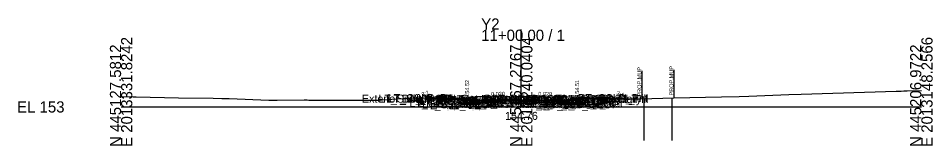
# Model space of a CAD drawing. Extents: x -26 to 203, y -10 to 6017.
# Drawn here: x -25.7 to 202.8, y 1990.3 to 2022.2 of the extents above; entities that cross this region are included whole.
import ezdxf

# ---------------------------------------------------------------- set-up
doc = ezdxf.new("R2010")
doc.units = 0
for name, color, linetype in [('Default', 7, 'Continuous'), ('Exist CMT Pavement', 7, 'Continuous'), ('Exist Cross Section Cell', 7, 'Continuous'), ('Exist XS Center Line Elevation Label', 7, 'Continuous'), ('Exist XS Ground Line', 7, 'Continuous'), ('Prop CMT Conc Surface', 7, 'Continuous'), ('Prop CMT Concrete Structures', 7, 'Continuous'), ('Prop CMT Pvmt Course 1', 7, 'Continuous'), ('Prop CMT Pvmt Course 1 CG', 7, 'Continuous'), ('Prop CMT Pvmt Course 1 Wedge', 7, 'Continuous'), ('Prop CMT Pvmt Course 2', 7, 'Continuous'), ('Prop CMT Pvmt Course 3', 7, 'Continuous'), ('Prop CMT Pvmt Surface', 7, 'Continuous'), ('Prop CMT Pvmt Wedge Surface 1', 7, 'Continuous'), ('Prop CMT Pvmt Wedge Surface 2', 7, 'Continuous'), ('Prop CMT Pvmt Wedge Surface 3', 7, 'Continuous'), ('Prop CMT Slope Grass', 7, 'Continuous'), ('Prop CMT Subgrade Earthwork', 7, 'Continuous'), ('Prop XS Earthwork Shape', 7, 'Continuous'), ('Prop XS Hydro Elevations', 7, 'Continuous'), ('Prop XS Label Text', 7, 'Continuous'), ('Prop XS SE Text', 7, 'Continuous'), ('Prop XS Side Slope Text', 7, 'Continuous'), ('Scratch_Level_0', 7, 'Continuous'), ('Scratch_Level_1', 7, 'Continuous')]:
    doc.layers.add(name, color=color, linetype=linetype)

msp = doc.modelspace()

# ---------------------------------------------------------------- linework, layer by layer
at = {"layer": 'Exist CMT Pavement'}
msp.add_lwpolyline([(89.49, 2001.72), (90.19, 2001.57), (91.02, 2001.56), (100, 2001.76), (100.76, 2001.78), (102.04, 2001.79), (110.95, 2001.68), (110.96, 2001.68)], dxfattribs=at)
at = {"layer": 'Exist Cross Section Cell'}
for p, q in [((100, 2000), (100, 2019.31)), ((0, 2000), (100, 2000)), ((100, 2000), (200, 2000))]:
    msp.add_line(p, q, dxfattribs=at)
at = {"layer": 'Exist XS Ground Line'}
msp.add_lwpolyline([(0, 2002.63), (2.99, 2002.56), (3.44, 2002.55), (3.78, 2002.54), (14.33, 2002.29), (22.98, 2002.18), (25.2, 2002.13), (26.49, 2002.12), (27.02, 2002.11), (36.96, 2001.73), (37.88, 2001.73), (39.03, 2001.72), (45.77, 2001.74), (46.15, 2001.74), (46.54, 2001.74), (46.94, 2001.73), (47.25, 2001.73), (53.38, 2001.7), (56.55, 2001.69), (57.92, 2001.68), (64.16, 2001.69), (68.82, 2002), (71.76, 2002.13), (87.86, 2001.87), (88.85, 2001.87), (90.19, 2001.57), (91.02, 2001.56), (100, 2001.76), (100.76, 2001.78), (102.04, 2001.79), (110.95, 2001.68), (112.62, 2001.98), (112.94, 2002.02), (114.7, 2002), (117.25, 2002.02), (122.01, 2002.03), (127.25, 2002.02), (129.89, 2002.02), (138.15, 2002.29), (150.06, 2002.49), (154.43, 2002.64), (156.88, 2002.69), (166.9, 2003.11), (169.95, 2003.21), (193.73, 2003.93), (194.93, 2003.97), (195.59, 2003.98), (196.48, 2004.04), (200, 2004.1)], dxfattribs=at)
at = {"layer": 'Prop CMT Conc Surface'}
for points in [[(86.49, 2001.52), (86.49, 2002.02), (85.99, 2002.02)], [(113.97, 2001.51), (113.97, 2002.01), (114.47, 2002.01)], [(88.49, 2001.64), (86.49, 2001.52)], [(111.97, 2001.63), (113.97, 2001.51)]]:
    msp.add_lwpolyline(points, dxfattribs=at)
at = {"layer": 'Prop CMT Concrete Structures'}
for points in [[(88.49, 2001.64), (86.49, 2001.52), (86.49, 2002.02), (85.99, 2002.02)], [(85.99, 2002.02), (85.99, 2001), (88.49, 2001.05)], [(111.97, 2001.63), (113.97, 2001.51), (113.97, 2002.01), (114.47, 2002.01)], [(114.47, 2002.01), (114.47, 2001), (111.97, 2001.05)], [(88.49, 2001.05), (88.49, 2001.64)], [(111.97, 2001.05), (111.97, 2001.63)]]:
    msp.add_lwpolyline(points, dxfattribs=at)
at = {"layer": 'Prop CMT Pvmt Course 1'}
for points in [[(100, 2001.87), (88.49, 2001.64)], [(88.49, 2001.64), (88.49, 2001.39)], [(88.49, 2001.39), (89.49, 2001.41)], [(89.49, 2001.53), (100, 2001.74)], [(89.49, 2001.41), (89.49, 2001.53)], [(100, 2001.62), (100, 2001.87)], [(100, 2001.87), (111.97, 2001.63)], [(100, 2001.62), (100, 2001.87)], [(100, 2001.74), (100, 2001.62), (100, 2001.62)], [(110.97, 2001.52), (100, 2001.74)], [(100, 2001.74), (100, 2001.62), (100, 2001.62)], [(110.97, 2001.4), (110.97, 2001.52)], [(111.97, 2001.38), (110.97, 2001.4)], [(111.97, 2001.63), (111.97, 2001.38)]]:
    msp.add_lwpolyline(points, dxfattribs=at)
at = {"layer": 'Prop CMT Pvmt Course 1 CG'}
for points in [[(88.49, 2001.05), (85.49, 2000.99), (85.15, 2000.65)], [(85.15, 2000.65), (88.49, 2000.72)], [(88.49, 2000.72), (88.49, 2001.05)], [(111.97, 2001.05), (114.97, 2000.99), (115.31, 2000.65)], [(111.97, 2000.71), (111.97, 2001.05)], [(115.31, 2000.65), (111.97, 2000.71)]]:
    msp.add_lwpolyline(points, dxfattribs=at)
at = {"layer": 'Prop CMT Pvmt Course 1 Wedge'}
for points in [[(92.23, 2001.59), (91.02, 2001.56), (90.93, 2001.56)], [(90.93, 2001.56), (91.02, 2001.56)], [(91.02, 2001.56), (92.23, 2001.59)]]:
    msp.add_lwpolyline(points, dxfattribs=at)
at = {"layer": 'Prop CMT Pvmt Course 2'}
for points in [[(89.49, 2001.41), (88.49, 2001.39)], [(88.49, 2001.39), (88.49, 2001.05)], [(88.49, 2001.05), (89.49, 2001.07)], [(89.49, 2001.07), (89.49, 2001.41)], [(110.97, 2001.07), (110.97, 2001.4)], [(110.97, 2001.4), (111.97, 2001.38)], [(111.97, 2001.05), (110.97, 2001.07)], [(111.97, 2001.38), (111.97, 2001.05)]]:
    msp.add_lwpolyline(points, dxfattribs=at)
at = {"layer": 'Prop CMT Pvmt Course 3'}
for points in [[(89.49, 2001.07), (88.49, 2001.05)], [(88.49, 2001.05), (88.49, 2000.72)], [(88.49, 2000.72), (89.49, 2000.74)], [(89.49, 2000.74), (89.49, 2001.07)], [(110.97, 2001.07), (111.97, 2001.05)], [(110.97, 2000.73), (110.97, 2001.07)], [(111.97, 2000.71), (110.97, 2000.73)], [(111.97, 2001.05), (111.97, 2000.71)]]:
    msp.add_lwpolyline(points, dxfattribs=at)
at = {"layer": 'Prop CMT Pvmt Surface'}
for points in [[(100, 2001.87), (88.49, 2001.64)], [(100, 2001.87), (111.97, 2001.63)]]:
    msp.add_lwpolyline(points, dxfattribs=at)
at = {"layer": 'Prop CMT Pvmt Wedge Surface 1'}
for points in [[(88.49, 2001.39), (88.49, 2001.64)], [(89.49, 2001.41), (88.49, 2001.39)], [(100, 2001.74), (89.49, 2001.53)], [(89.49, 2001.53), (89.49, 2001.41)], [(100, 2001.74), (110.97, 2001.52)], [(110.97, 2001.52), (110.97, 2001.4)], [(110.97, 2001.4), (111.97, 2001.38)], [(111.97, 2001.38), (111.97, 2001.63)]]:
    msp.add_lwpolyline(points, dxfattribs=at)
at = {"layer": 'Prop CMT Pvmt Wedge Surface 2'}
for points in [[(88.49, 2001.39), (88.49, 2001.64)], [(100, 2001.62), (88.49, 2001.39)], [(100, 2001.62), (111.97, 2001.38)], [(111.97, 2001.38), (111.97, 2001.63)]]:
    msp.add_lwpolyline(points, dxfattribs=at)
at = {"layer": 'Prop CMT Pvmt Wedge Surface 3'}
for points in [[(88.49, 2001.05), (88.49, 2001.64)], [(100, 2001.28), (88.49, 2001.05)], [(100, 2001.28), (111.97, 2001.05)], [(111.97, 2001.05), (111.97, 2001.63)]]:
    msp.add_lwpolyline(points, dxfattribs=at)
at = {"layer": 'Prop CMT Slope Grass'}
for points in [[(85.99, 2002.02), (76.49, 2002.21), (76.05, 2002.06)], [(114.47, 2002.01), (123.97, 2002.2), (124.5, 2002.02)]]:
    msp.add_lwpolyline(points, dxfattribs=at)
at = {"layer": 'Prop CMT Subgrade Earthwork'}
for points in [[(88.49, 2000.72), (85.15, 2000.65), (83.74, 2002.06)], [(111.97, 2000.71), (115.31, 2000.65), (116.72, 2002.05)], [(89.49, 2000.74), (88.49, 2000.72)], [(89.49, 2000.74), (89.49, 2001.72)], [(110.97, 2000.73), (110.96, 2001.68)], [(110.97, 2000.73), (111.97, 2000.71)]]:
    msp.add_lwpolyline(points, dxfattribs=at)
at = {"layer": 'Prop XS Earthwork Shape'}
for points in [[(76.49, 2002.21), (76.05, 2002.06), (83.87, 2001.94), (83.74, 2002.06)], [(76.49, 2002.21), (76.05, 2002.06), (83.87, 2001.94), (83.74, 2002.06)], [(83.87, 2001.94), (83.74, 2002.06), (76.49, 2002.21), (76.05, 2002.06)], [(83.87, 2001.94), (83.74, 2002.06), (76.49, 2002.21), (76.05, 2002.06)], [(111.97, 2001.63), (113.97, 2001.51), (113.97, 2002.01), (112.94, 2002.02), (112.62, 2001.98), (110.96, 2001.68), (110.96, 2001.65)], [(111.97, 2001.63), (113.97, 2001.51), (113.97, 2002.01), (112.94, 2002.02), (112.62, 2001.98), (110.96, 2001.68), (110.96, 2001.65)], [(111.97, 2001.63), (113.97, 2001.51), (113.97, 2002.01), (112.94, 2002.02), (112.62, 2001.98), (110.96, 2001.68), (110.96, 2001.65)], [(111.97, 2001.63), (113.97, 2001.51), (113.97, 2002.01), (112.94, 2002.02), (112.62, 2001.98), (110.96, 2001.68), (110.96, 2001.65)], [(110.97, 2000.73), (110.96, 2001.65), (111.97, 2001.63), (111.97, 2001.05), (114.47, 2001), (114.47, 2002.01), (114.7, 2002), (116.68, 2002.01), (115.31, 2000.65), (111.97, 2000.71)], [(110.97, 2000.73), (110.96, 2001.65), (111.97, 2001.63), (111.97, 2001.05), (114.47, 2001), (114.47, 2002.01), (114.7, 2002), (116.68, 2002.01), (115.31, 2000.65), (111.97, 2000.71)], [(110.97, 2000.73), (110.96, 2001.65), (111.97, 2001.63), (111.97, 2001.05), (114.47, 2001), (114.47, 2002.01), (114.7, 2002), (116.68, 2002.01), (115.31, 2000.65), (111.97, 2000.71)], [(110.97, 2000.73), (110.96, 2001.65), (111.97, 2001.63), (111.97, 2001.05), (114.47, 2001), (114.47, 2002.01), (114.7, 2002), (116.68, 2002.01), (115.31, 2000.65), (111.97, 2000.71)], [(111.97, 2001.63), (113.97, 2001.51), (113.97, 2002.01), (114.47, 2002.01), (114.47, 2001), (111.97, 2001.05)], [(111.97, 2001.05), (111.97, 2001.63), (113.97, 2001.51), (113.97, 2002.01), (114.47, 2002.01), (114.47, 2001)], [(111.97, 2001.63), (113.97, 2001.51), (113.97, 2002.01), (114.47, 2002.01), (114.47, 2001), (111.97, 2001.05)], [(111.97, 2001.63), (113.97, 2001.51), (113.97, 2002.01), (114.47, 2002.01), (114.47, 2001), (111.97, 2001.05)], [(116.68, 2002.01), (116.72, 2002.05), (123.97, 2002.2), (124.5, 2002.02), (122.01, 2002.03), (117.25, 2002.02)], [(122.01, 2002.03), (124.5, 2002.02), (123.97, 2002.2), (116.72, 2002.05), (116.68, 2002.01), (117.25, 2002.02)], [(116.68, 2002.01), (116.72, 2002.05), (123.97, 2002.2), (124.5, 2002.02), (122.01, 2002.03), (117.25, 2002.02)], [(116.68, 2002.01), (116.72, 2002.05), (123.97, 2002.2), (124.5, 2002.02), (122.01, 2002.03), (117.25, 2002.02)], [(85.99, 2001), (88.49, 2001.05), (88.49, 2001.64), (89.49, 2001.66), (89.49, 2000.74), (88.49, 2000.72), (85.15, 2000.65), (83.87, 2001.94), (85.99, 2001.9)], [(89.49, 2000.74), (88.49, 2000.72), (85.15, 2000.65), (83.87, 2001.94), (85.99, 2001.9), (85.99, 2001), (88.49, 2001.05), (88.49, 2001.64), (89.49, 2001.66)], [(85.99, 2001), (88.49, 2001.05), (88.49, 2001.64), (89.49, 2001.66), (89.49, 2000.74), (88.49, 2000.72), (85.15, 2000.65), (83.87, 2001.94), (85.99, 2001.9)], [(89.49, 2000.74), (88.49, 2000.72), (85.15, 2000.65), (83.87, 2001.94), (85.99, 2001.9), (85.99, 2001), (88.49, 2001.05), (88.49, 2001.64), (89.49, 2001.66)], [(85.99, 2001), (88.49, 2001.05), (88.49, 2001.64), (86.49, 2001.52), (86.49, 2001.89), (85.99, 2001.9)], [(85.99, 2001.9), (86.49, 2001.89), (86.49, 2001.52), (88.49, 2001.64), (88.49, 2001.05), (85.99, 2001)], [(85.99, 2001.9), (86.49, 2001.89), (86.49, 2001.52), (88.49, 2001.64), (88.49, 2001.05), (85.99, 2001)], [(85.99, 2001), (88.49, 2001.05), (88.49, 2001.64), (86.49, 2001.52), (86.49, 2001.89), (85.99, 2001.9)], [(89.49, 2001.66), (89.49, 2001.72), (88.85, 2001.87), (87.86, 2001.87), (86.49, 2001.89), (86.49, 2001.52), (88.49, 2001.64)], [(89.49, 2001.66), (89.49, 2001.72), (88.85, 2001.87), (87.86, 2001.87), (86.49, 2001.89), (86.49, 2001.52), (88.49, 2001.64)], [(89.49, 2001.66), (89.49, 2001.72), (88.85, 2001.87), (87.86, 2001.87), (86.49, 2001.89), (86.49, 2001.52), (88.49, 2001.64)], [(89.49, 2001.66), (89.49, 2001.72), (88.85, 2001.87), (87.86, 2001.87), (86.49, 2001.89), (86.49, 2001.52), (88.49, 2001.64)], [(89.49, 2001.66), (89.49, 2001.72), (89.77, 2001.66)], [(89.49, 2001.66), (89.49, 2001.72), (89.77, 2001.66)], [(89.49, 2001.66), (89.49, 2001.72), (89.77, 2001.66)], [(89.49, 2001.66), (89.49, 2001.72), (89.77, 2001.66)], [(107.25, 2001.72), (110.96, 2001.65), (110.96, 2001.68), (110.95, 2001.68)], [(107.25, 2001.72), (110.96, 2001.65), (110.96, 2001.68), (110.95, 2001.68)], [(107.25, 2001.72), (110.96, 2001.65), (110.96, 2001.68), (110.95, 2001.68)], [(107.25, 2001.72), (110.96, 2001.65), (110.96, 2001.68), (110.95, 2001.68)]]:
    msp.add_lwpolyline(points, close=True, dxfattribs=at)
at = {"layer": 'Prop XS Label Text'}
for p, q in [((130.12, 2009.02), (130.12, 2002.02)), ((138.12, 2009.29), (138.12, 2002.29))]:
    msp.add_line(p, q, dxfattribs=at)
at = {"layer": 'Scratch_Level_1'}
for p, q in [((130.62, 2002.04), (130.62, 1991.62)), ((137.62, 2002.28), (137.62, 1991.62))]:
    msp.add_line(p, q, dxfattribs=at)

# ---------------------------------------------------------------- texts
at = {"layer": 'Default'}
msp.add_text('-', height=0.0001, dxfattribs=at).set_placement((0, 2000))
at = {"layer": 'Exist Cross Section Cell'}
for s, p in [('Y2', (90, 2019.31)), ('11+00.00 / 1', (90, 2016.51)), ('EL 153', (-26, 1998.6))]:
    msp.add_text(s, height=2.8, dxfattribs=at).set_placement(p)
for s, p in [('E 2013331.8242', (2.8, 1990)), ('E 2013240.0404', (102.8, 1990)), ('E 2013148.2566', (202.8, 1990)), ('N 445127.5812', (0, 1990)), ('N 445167.2767', (100, 1990)), ('N 445206.9722', (200, 1990))]:
    msp.add_text(s, height=2.8, rotation=90, dxfattribs=at).set_placement(p)
at = {"layer": 'Exist XS Center Line Elevation Label'}
msp.add_text('154.76', height=2, dxfattribs=at).set_placement((95.97, 1996.76))
at = {"layer": 'Prop XS Hydro Elevations'}
for s, p in [('154.52', (86.99, 2002.52)), ('154.51', (114.47, 2002.51))]:
    msp.add_text(s, height=1, rotation=90, dxfattribs=at).set_placement(p)
at = {"layer": 'Prop XS Label Text'}
for p in [(130.02, 2002.6), (138.02, 2002.86)]:
    msp.add_text('PROP.MUP', height=1, rotation=90, dxfattribs=at).set_placement(p)
at = {"layer": 'Prop XS SE Text'}
for rotation, p in [(1.1458, (92.48, 2002.72)), (358.8542, (104.26, 2002.78))]:
    msp.add_text('0.020', height=1, rotation=rotation, dxfattribs=at).set_placement(p)
at = {"layer": 'Prop XS Side Slope Text'}
for rotation, p in [(18.4332, (75.28, 2002.6)), (341.5668, (123.72, 2003.07))]:
    msp.add_text('3:1', height=1, rotation=rotation, dxfattribs=at).set_placement(p)
at = {"layer": 'Scratch_Level_0'}
for s, p in [('Exterior Boundary', (60.19, 2001.06)), ('LT_Sub_Trench_Out_DLT', (64.31, 2001.06)), ('LT_Slope_Fill', (66.57, 2001.06)), ('LT_CSLP_Pnt', (66.66, 2001.21)), ('LT_CG1_Shelf_Out', (72.04, 1999.99)), ('LT_CG_Top_Face', (73.75, 2001.02)), ('LT_CG_Top_BOC', (74.27, 2001.02)), ('LT_CG_Bot_BOC', (74.31, 2000)), ('LT_PV_Sub_Tie_Out', (74.45, 2000.72)), ('LT_CG_Top_Gut', (74.73, 2000.52)), ('LT_PV_OEEOP_EG', (77.04, 2000.73)), ('LT_CG_Bot_IE', (78.4, 2000.05)), ('LT_PV2_OEOT', (78.66, 2000.39)), ('LT_PV3_OEOT', (78.66, 2000.05)), ('LT_PV2_OEEOP', (78.8, 2000.41)), ('LT_PV3_OEEOP', (78.8, 2000.07)), ('LT_PV1_OEOT', (79.23, 2000.64)), ('LT_PV1_OEEOP', (79.37, 2000.53)), ('RT_PV_IEEOP_EG', (88.14, 2000.76)), ('LT_PV_IEEOP_EG', (88.19, 2000.76)), ('RT_PV2_IEEOP', (89.91, 2000.62)), ('RT_PV3_IEEOP', (89.91, 2000.28)), ('LT_PV2_IEEOP', (89.95, 2000.62)), ('LT_PV3_IEEOP', (89.95, 2000.28)), ('RT_PV1_IEEOP', (90.47, 2000.74)), ('LT_PV1_IEEOP', (90.52, 2000.74)), ('PV2_PGL', (93.91, 2000.62)), ('PV1_PGL', (94.47, 2000.87)), ('RT_PV_Sub_Tie_Out', (95.85, 2000.68)), ('RT_Sub_Trench_Out_DLT', (97.24, 2001.05)), ('RT_PV_OEEOP_EG', (98.47, 2000.68)), ('RT_PV2_OEEOP', (100.23, 2000.4)), ('RT_PV3_OEEOP', (100.23, 2000.07)), ('RT_PV1_OEEOP', (100.8, 2000.52)), ('RT_CG_Top_Face', (101.19, 2001.01)), ('RT_CG1_Shelf_Out', (101.48, 1999.99)), ('RT_CG_Bot_IE', (101.84, 2000.05)), ('RT_PV2_OEOT', (102.1, 2000.38)), ('RT_PV3_OEOT', (102.1, 2000.05)), ('RT_CG_Top_Gut', (102.16, 2000.51)), ('RT_PV1_OEOT', (102.67, 2000.63)), ('RT_CG_Top_BOC', (102.71, 2001.01)), ('RT_CG_Bot_BOC', (102.74, 2000)), ('Exterior Boundary', (108.64, 2001.02)), ('RT_CSLP_Pnt', (114.1, 2001.2)), ('RT_Slope_Fill', (114.97, 2001.02)), ('LT_Sub_OEOP', (75.26, 1999.65)), ('LT_Sub_OEOT', (78.57, 1999.72)), ('LT_Sub_OEEOP', (78.71, 1999.74)), ('RT_Sub_OEEOP', (100.14, 1999.73)), ('RT_Sub_OEOT', (102.01, 1999.71)), ('RT_Sub_OEOP', (105.38, 1999.65))]:
    msp.add_text(s, height=2, dxfattribs=at).set_placement(p)

doc.saveas('drawing.dxf')
